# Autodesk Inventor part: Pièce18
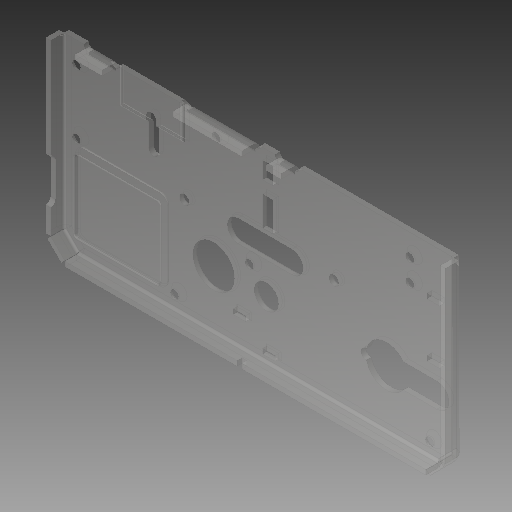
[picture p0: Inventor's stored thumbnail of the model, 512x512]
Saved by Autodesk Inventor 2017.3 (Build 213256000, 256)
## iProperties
Created: 2007-12
Part Number: Pièce18
Material: Générique
Document SubType Name: Modeling
Designer: ficho
Density: 1 g/cm^3
Appearance: Par défaut
Author: ficho
Sending System: SolidWorks 2009
Last Author: christophe
Last Saved: 2011-02-10
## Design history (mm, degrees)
feature "Enlèv. mat.-Extru.26"
node "Solide1"
